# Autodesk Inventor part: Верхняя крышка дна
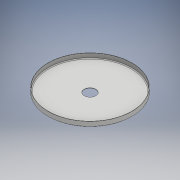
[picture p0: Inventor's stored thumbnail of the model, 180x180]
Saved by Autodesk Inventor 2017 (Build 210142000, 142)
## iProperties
Part Number: Верхняя крышка дна
Material: Типовые
Document SubType Name: Modeling
Designer: MaxZam
Density: 1 g/cm^3
Appearance: По умолчанию
Author: MaxZam
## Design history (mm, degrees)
sketch "Эскиз1"
  geometry: C1 r 225 at (0, 0); C2 r 31 at (0, 0); 1 further point
  constraints: 2 centre point, 2 coincident
  dimensions: "d0" = 450 diameter of C1; "d1" = 62 diameter of C2
extrude "Выдавливание1" new body sketch "Эскиз1" distance "d2" = 1.8; taper "d3" = 0 deg
sketch "Эскиз2"
  geometry: C1 r 31 at (0, 0) reference; C2 r 225 at (0, 0); C3 r 223.5 at (0, 0); 1 further point
  constraints: 2 centre point, 2 coincident
  dimensions: "d4" = 447 diameter of C3
extrude "Выдавливание2" join sketch "Эскиз2" distance "d5" = 25; taper "d6" = 0 deg
fillet "Сопряжение1" dims "d7" = 4
node "Твердое тело1"
